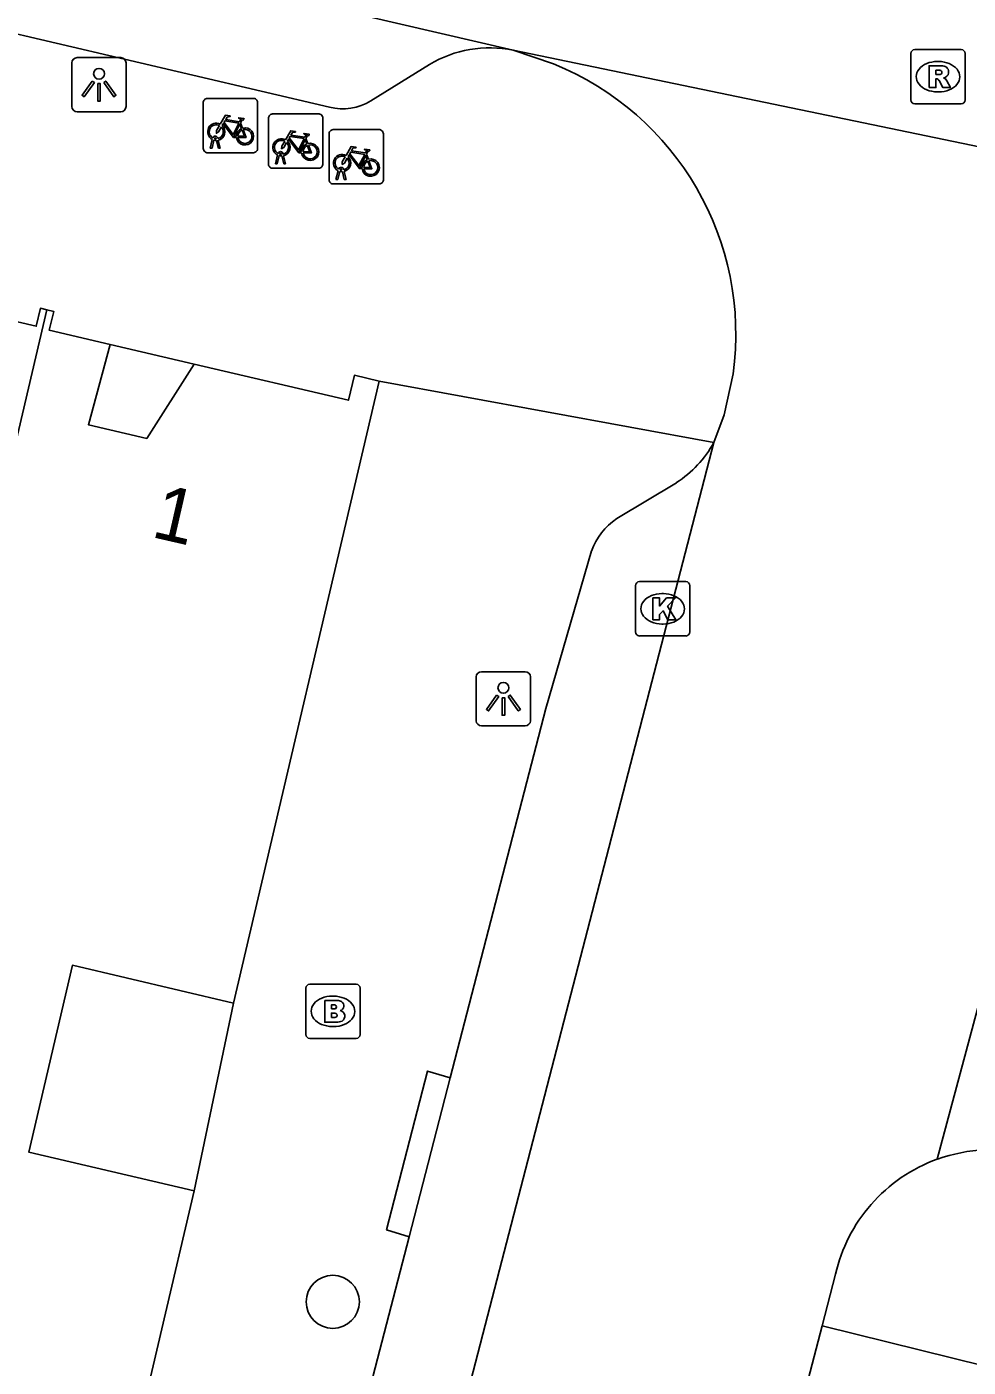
# Model space of a CAD drawing. Extents: x 163686 to 164493, y 382719 to 383870.
# Drawn here: x 163954.4 to 163971.73, y 383281.87 to 383306.54 of the extents above; entities that cross this region are included whole.
import ezdxf

# ---------------------------------------------------------------- set-up
doc = ezdxf.new("R2010")
doc.units = 0
for name, color, linetype in [('IMGEO_Boom', 7, 'Continuous'), ('IMGEO_Brandkraan', 7, 'Continuous'), ('IMGEO_Fietsenrek', 7, 'Continuous'), ('IMGEO_Groenvoorziening', 7, 'Continuous'), ('IMGEO_Kolk', 7, 'Continuous'), ('IMGEO_Lichtpunt', 7, 'Continuous'), ('IMGEO_Pand', 7, 'Continuous'), ('IMGEO_Pand_nummerreeks', 7, 'Continuous'), ('IMGEO_Pand_overbouw', 7, 'Continuous'), ('IMGEO_Rijbaan_lokaal_open', 7, 'Continuous'), ('IMGEO_Rioolput', 7, 'Continuous'), ('IMGEO_Voetpad_open', 7, 'Continuous')]:
    doc.layers.add(name, color=color, linetype=linetype)

msp = doc.modelspace()

# ---------------------------------------------------------------- linework, layer by layer
at = {"layer": 'IMGEO_Boom'}
msp.add_circle((163960.029, 383283.075), 0.489, dxfattribs=at)
at = {"layer": 'IMGEO_Brandkraan'}
for p, q in [((163959.532, 383287.995), (163959.532, 383288.847)), ((163959.607, 383288.921), (163960.459, 383288.921)), ((163960.533, 383288.847), (163960.533, 383287.995)), ((163960.02, 383288.701), (163960.045, 383288.701)), ((163960.043, 383288.141), (163960.018, 383288.141)), ((163960.459, 383287.921), (163959.607, 383287.921))]:
    msp.add_line(p, q, dxfattribs=at)
for points in [[(163959.532, 383287.995), (163959.532, 383288.847)], [(163959.607, 383288.921), (163960.459, 383288.921)], [(163960.533, 383288.847), (163960.533, 383287.995)], [(163959.88, 383288.621), (163959.88, 383288.221), (163960.093, 383288.221)], [(163960.111, 383288.621), (163959.88, 383288.621)], [(163960.059, 383288.54), (163960.005, 383288.54), (163960.005, 383288.464)], [(163960.005, 383288.464), (163960.058, 383288.464)], [(163960.067, 383288.388), (163960.005, 383288.388), (163960.005, 383288.307)], [(163960.005, 383288.307), (163960.067, 383288.307)], [(163960.459, 383287.921), (163959.607, 383287.921)]]:
    msp.add_lwpolyline(points, dxfattribs=at)
for centre, radius, start, end in [((163959.609, 383288.845), 0.0765, 91.552, 178.448), ((163959.609, 383288.845), 0.0765, 91.552, 178.448), ((163960.457, 383288.845), 0.0765, 1.552, 88.448), ((163960.457, 383288.845), 0.0765, 1.552, 88.448), ((163960.115, 383288.476), 0.145, 59.4692, 91.5367), ((163960.14, 383288.523), 0.0922, 285.5137, 58.1501), ((163960.06, 383288.502), 0.0379, 267.8285, 90.9355), ((163960.068, 383288.347), 0.0404, 269.8759, 90.5077), ((163960.145, 383288.331), 0.105, 301.3115, 78.989), ((163960.099, 383288.472), 0.251, 268.6676, 293.5347), ((163959.609, 383287.997), 0.0765, 181.552, 268.448), ((163959.609, 383287.997), 0.0765, 181.552, 268.448), ((163960.457, 383287.997), 0.0765, 271.552, 358.448), ((163960.457, 383287.997), 0.0765, 271.552, 358.448)]:
    msp.add_arc(centre, radius, start, end, dxfattribs=at)
for centre, major_axis, ratio, start_param, end_param in [((163960.019, 383288.421), (-0.387, 0.002), 0.722429, 4.712389, 7.853982), ((163960.044, 383288.421), (-0.39, 0.002), 0.717154, 1.570796, 4.712389)]:
    msp.add_ellipse(centre, major_axis=major_axis, ratio=ratio, start_param=start_param, end_param=end_param, dxfattribs=at)
at = {"layer": 'IMGEO_Fietsenrek'}
for p, q in [((163957.645, 383304.298), (163957.645, 383305.139)), ((163957.645, 383305.139), (163957.645, 383304.298)), ((163957.72, 383305.223), (163958.561, 383305.223)), ((163958.561, 383305.223), (163957.72, 383305.223)), ((163958.645, 383305.148), (163958.645, 383304.307)), ((163958.645, 383304.307), (163958.645, 383305.148)), ((163958.921, 383304.937), (163959.762, 383304.937)), ((163959.762, 383304.937), (163958.921, 383304.937)), ((163958.332, 383304.772), (163958.368, 383304.677)), ((163958.846, 383304.012), (163958.846, 383304.853)), ((163958.846, 383304.853), (163958.846, 383304.012)), ((163959.846, 383304.862), (163959.846, 383304.021)), ((163959.846, 383304.021), (163959.846, 383304.862)), ((163960.036, 383304.648), (163960.877, 383304.648)), ((163960.877, 383304.648), (163960.036, 383304.648)), ((163957.772, 383304.307), (163957.811, 383304.467)), ((163957.841, 383304.455), (163957.806, 383304.307)), ((163957.883, 383304.479), (163957.882, 383304.483)), ((163957.924, 383304.307), (163957.89, 383304.449)), ((163957.914, 383304.49), (163957.915, 383304.483)), ((163957.922, 383304.453), (163957.957, 383304.307)), ((163959.533, 383304.486), (163959.569, 383304.391)), ((163959.961, 383303.723), (163959.961, 383304.564)), ((163959.961, 383304.564), (163959.961, 383303.723)), ((163960.961, 383304.573), (163960.961, 383303.732)), ((163960.961, 383303.732), (163960.961, 383304.573)), ((163958.57, 383304.223), (163957.729, 383304.223)), ((163957.729, 383304.223), (163958.57, 383304.223)), ((163957.806, 383304.307), (163957.772, 383304.307)), ((163957.957, 383304.307), (163957.924, 383304.307)), ((163958.973, 383304.021), (163959.012, 383304.181)), ((163959.042, 383304.169), (163959.007, 383304.021)), ((163959.084, 383304.193), (163959.083, 383304.197)), ((163959.125, 383304.021), (163959.091, 383304.163)), ((163959.115, 383304.204), (163959.116, 383304.197)), ((163959.123, 383304.167), (163959.158, 383304.021)), ((163960.648, 383304.197), (163960.684, 383304.102)), ((163959.771, 383303.937), (163958.93, 383303.937)), ((163958.93, 383303.937), (163959.771, 383303.937)), ((163959.007, 383304.021), (163958.973, 383304.021)), ((163959.158, 383304.021), (163959.125, 383304.021)), ((163960.088, 383303.732), (163960.127, 383303.892)), ((163960.157, 383303.88), (163960.122, 383303.732)), ((163960.199, 383303.904), (163960.198, 383303.908)), ((163960.23, 383303.915), (163960.231, 383303.908)), ((163960.238, 383303.878), (163960.273, 383303.732)), ((163960.886, 383303.648), (163960.045, 383303.648)), ((163960.045, 383303.648), (163960.886, 383303.648)), ((163960.122, 383303.732), (163960.088, 383303.732)), ((163960.24, 383303.732), (163960.206, 383303.874)), ((163960.273, 383303.732), (163960.24, 383303.732))]:
    msp.add_line(p, q, dxfattribs=at)
for points in [[(163957.958, 383304.749), (163958.053, 383304.913), (163958.139, 383304.899), (163958.141, 383304.89), (163958.085, 383304.879), (163958.058, 383304.834), (163958.314, 383304.793)], [(163958.314, 383304.793), (163958.339, 383304.842), (163958.333, 383304.846), (163958.31, 383304.85), (163958.298, 383304.857), (163958.297, 383304.86), (163958.299, 383304.865), (163958.394, 383304.85), (163958.396, 383304.84), (163958.386, 383304.827), (163958.374, 383304.821), (163958.36, 383304.827), (163958.332, 383304.772)], [(163957.979, 383304.697), (163957.927, 383304.607), (163957.887, 383304.582), (163957.888, 383304.629), (163957.943, 383304.723)], [(163958.254, 383304.505), (163958.204, 383304.505), (163958.013, 383304.756), (163957.994, 383304.724)], [(163958.301, 383304.768), (163958.044, 383304.809), (163958.027, 383304.78), (163958.194, 383304.56), (163958.301, 383304.768)], [(163958.349, 383304.67), (163958.319, 383304.747), (163958.21, 383304.529), (163958.253, 383304.529)], [(163958.283, 383304.529), (163958.403, 383304.528), (163958.359, 383304.642)], [(163958.379, 383304.649), (163958.434, 383304.504), (163958.284, 383304.504)], [(163959.159, 383304.463), (163959.254, 383304.627), (163959.34, 383304.613), (163959.342, 383304.604), (163959.286, 383304.593), (163959.259, 383304.548), (163959.515, 383304.507)], [(163959.18, 383304.411), (163959.128, 383304.321), (163959.088, 383304.296), (163959.089, 383304.343), (163959.144, 383304.437)], [(163959.455, 383304.219), (163959.405, 383304.219), (163959.214, 383304.47), (163959.195, 383304.438)], [(163959.502, 383304.482), (163959.245, 383304.523), (163959.228, 383304.494), (163959.395, 383304.274), (163959.502, 383304.482)], [(163959.55, 383304.384), (163959.52, 383304.461), (163959.411, 383304.243), (163959.454, 383304.243)], [(163959.515, 383304.507), (163959.54, 383304.556), (163959.534, 383304.56), (163959.511, 383304.564), (163959.499, 383304.571), (163959.498, 383304.574), (163959.5, 383304.579), (163959.595, 383304.564), (163959.597, 383304.554), (163959.587, 383304.541), (163959.575, 383304.535), (163959.561, 383304.541), (163959.533, 383304.486)], [(163959.484, 383304.243), (163959.604, 383304.242), (163959.56, 383304.356)], [(163959.58, 383304.363), (163959.635, 383304.218), (163959.485, 383304.218)], [(163960.295, 383304.122), (163960.243, 383304.032), (163960.203, 383304.007), (163960.204, 383304.054), (163960.259, 383304.148)], [(163960.274, 383304.174), (163960.369, 383304.338), (163960.455, 383304.324), (163960.457, 383304.315), (163960.401, 383304.304), (163960.374, 383304.259), (163960.63, 383304.218)], [(163960.57, 383303.93), (163960.52, 383303.93), (163960.329, 383304.181), (163960.31, 383304.149)], [(163960.617, 383304.193), (163960.36, 383304.234), (163960.343, 383304.205), (163960.51, 383303.985), (163960.617, 383304.193)], [(163960.665, 383304.095), (163960.635, 383304.172), (163960.526, 383303.954), (163960.569, 383303.954)], [(163960.63, 383304.218), (163960.655, 383304.267), (163960.649, 383304.271), (163960.626, 383304.275), (163960.614, 383304.282), (163960.613, 383304.285), (163960.615, 383304.29), (163960.71, 383304.275), (163960.712, 383304.265), (163960.702, 383304.252), (163960.69, 383304.246), (163960.676, 383304.252), (163960.648, 383304.197)], [(163960.599, 383303.954), (163960.719, 383303.953), (163960.675, 383304.067)], [(163960.695, 383304.074), (163960.75, 383303.929), (163960.6, 383303.929)]]:
    msp.add_lwpolyline(points, dxfattribs=at)
for centre, radius, start, end in [((163957.723, 383305.145), 0.0779, 92.4484, 184.2845), ((163957.723, 383305.145), 0.0779, 92.4484, 184.2845), ((163958.567, 383305.145), 0.0779, 2.4484, 94.2845), ((163958.567, 383305.145), 0.0779, 2.4484, 94.2845), ((163958.924, 383304.859), 0.0779, 92.4484, 184.2845), ((163958.924, 383304.859), 0.0779, 92.4484, 184.2845), ((163959.768, 383304.859), 0.0779, 2.4484, 94.2845), ((163959.768, 383304.859), 0.0779, 2.4484, 94.2845), ((163957.885, 383304.608), 0.159, 62.6766, 242.1369), ((163957.885, 383304.608), 0.129, 63.3192, 238.903), ((163957.885, 383304.608), 0.129, 283.6043, 43.4302), ((163957.885, 383304.608), 0.159, 283.5766, 46.6042), ((163958.412, 383304.524), 0.159, 113.3408, 178.3217), ((163958.412, 383304.524), 0.159, 187.0065, 105.7708), ((163958.412, 383304.524), 0.129, 113.923, 177.9556), ((163958.412, 383304.524), 0.129, 188.6715, 104.5883), ((163960.039, 383304.57), 0.0779, 92.4484, 184.2845), ((163960.039, 383304.57), 0.0779, 92.4484, 184.2845), ((163960.883, 383304.57), 0.0779, 2.4484, 94.2845), ((163960.883, 383304.57), 0.0779, 2.4484, 94.2845), ((163957.865, 383304.479), 0.0499, 12.8025, 158.6934), ((163957.885, 383304.608), 0.159, 253.9967, 271.7867), ((163957.865, 383304.479), 0.0174, 12.8025, 163.4502), ((163957.885, 383304.608), 0.129, 253.415, 269.0204), ((163959.086, 383304.322), 0.159, 62.6766, 242.1369), ((163959.086, 383304.322), 0.129, 63.3192, 238.903), ((163959.086, 383304.322), 0.129, 283.6043, 43.4302), ((163959.086, 383304.322), 0.159, 283.5766, 46.6042), ((163959.613, 383304.238), 0.159, 113.3408, 178.3217), ((163959.613, 383304.238), 0.159, 187.0065, 105.7708), ((163957.723, 383304.301), 0.0779, 182.4484, 274.2845), ((163957.723, 383304.301), 0.0779, 182.4484, 274.2845), ((163958.567, 383304.301), 0.0779, 272.4484, 4.2845), ((163958.567, 383304.301), 0.0779, 272.4484, 4.2845), ((163959.066, 383304.193), 0.0499, 12.8025, 158.6934), ((163959.086, 383304.322), 0.159, 253.9967, 271.7867), ((163959.066, 383304.193), 0.0174, 12.8025, 163.4502), ((163959.086, 383304.322), 0.129, 253.415, 269.0204), ((163959.613, 383304.238), 0.129, 113.923, 177.9556), ((163959.613, 383304.238), 0.129, 188.6715, 104.5883), ((163960.201, 383304.033), 0.159, 62.6766, 242.1369), ((163960.201, 383304.033), 0.129, 63.3192, 238.903), ((163960.201, 383304.033), 0.159, 283.5766, 46.6042), ((163958.924, 383304.015), 0.0779, 182.4484, 274.2845), ((163958.924, 383304.015), 0.0779, 182.4484, 274.2845), ((163959.768, 383304.015), 0.0779, 272.4484, 4.2845), ((163959.768, 383304.015), 0.0779, 272.4484, 4.2845), ((163960.181, 383303.904), 0.0499, 12.8025, 158.6934), ((163960.201, 383304.033), 0.159, 253.9967, 271.7867), ((163960.181, 383303.904), 0.0174, 12.8025, 163.4502), ((163960.201, 383304.033), 0.129, 253.415, 269.0204), ((163960.201, 383304.033), 0.129, 283.6043, 43.4302), ((163960.728, 383303.949), 0.159, 113.3408, 178.3217), ((163960.728, 383303.949), 0.159, 187.0065, 105.7708), ((163960.728, 383303.949), 0.129, 113.923, 177.9556), ((163960.728, 383303.949), 0.129, 188.6715, 104.5883), ((163960.039, 383303.726), 0.0779, 182.4484, 274.2845), ((163960.039, 383303.726), 0.0779, 182.4484, 274.2845), ((163960.883, 383303.726), 0.0779, 272.4484, 4.2845), ((163960.883, 383303.726), 0.0779, 272.4484, 4.2845)]:
    msp.add_arc(centre, radius, start, end, dxfattribs=at)
at = {"layer": 'IMGEO_Groenvoorziening'}
msp.add_lwpolyline([(163969.037, 383282.636), (163976.803, 383280.714)], dxfattribs=at)
at = {"layer": 'IMGEO_Kolk'}
for p, q in [((163965.601, 383295.403), (163965.601, 383296.255)), ((163965.676, 383296.329), (163966.528, 383296.329)), ((163966.602, 383296.255), (163966.602, 383295.403)), ((163966.089, 383296.109), (163966.114, 383296.109)), ((163966.112, 383295.549), (163966.087, 383295.549)), ((163966.528, 383295.329), (163965.676, 383295.329))]:
    msp.add_line(p, q, dxfattribs=at)
for points in [[(163965.601, 383295.403), (163965.601, 383296.255)], [(163965.676, 383296.329), (163966.528, 383296.329)], [(163966.602, 383296.255), (163966.602, 383295.403)], [(163965.922, 383296.029), (163966.045, 383296.029), (163966.045, 383295.878), (163966.175, 383296.029), (163966.339, 383296.029), (163966.193, 383295.878), (163966.346, 383295.629), (163966.194, 383295.629), (163966.109, 383295.793), (163966.045, 383295.726), (163966.045, 383295.629), (163965.922, 383295.629), (163965.922, 383296.029)], [(163966.528, 383295.329), (163965.676, 383295.329)]]:
    msp.add_lwpolyline(points, dxfattribs=at)
for centre, start, end in [((163965.678, 383296.253), 91.552, 178.448), ((163965.678, 383296.253), 91.552, 178.448), ((163966.526, 383296.253), 1.552, 88.448), ((163966.526, 383296.253), 1.552, 88.448), ((163965.678, 383295.405), 181.552, 268.448), ((163965.678, 383295.405), 181.552, 268.448), ((163966.526, 383295.405), 271.552, 358.448), ((163966.526, 383295.405), 271.552, 358.448)]:
    msp.add_arc(centre, 0.0765, start, end, dxfattribs=at)
for centre, major_axis, ratio, start_param, end_param in [((163966.088, 383295.829), (-0.387, 0.002), 0.722429, 4.712389, 7.853982), ((163966.113, 383295.829), (-0.39, 0.002), 0.717154, 1.570796, 4.712389)]:
    msp.add_ellipse(centre, major_axis=major_axis, ratio=ratio, start_param=start_param, end_param=end_param, dxfattribs=at)
at = {"layer": 'IMGEO_Lichtpunt'}
for p, q in [((163955.227, 383305.878), (163955.227, 383305.071)), ((163955.227, 383305.878), (163955.227, 383305.071)), ((163956.129, 383305.973), (163955.321, 383305.973)), ((163956.129, 383305.973), (163955.321, 383305.973)), ((163956.223, 383305.071), (163956.223, 383305.878)), ((163956.223, 383305.071), (163956.223, 383305.878)), ((163955.321, 383304.977), (163956.129, 383304.977)), ((163955.321, 383304.977), (163956.129, 383304.977)), ((163962.671, 383294.577), (163962.671, 383293.77)), ((163962.671, 383294.577), (163962.671, 383293.77)), ((163963.573, 383294.672), (163962.765, 383294.672)), ((163963.573, 383294.672), (163962.765, 383294.672)), ((163963.667, 383293.77), (163963.667, 383294.577)), ((163963.667, 383293.77), (163963.667, 383294.577)), ((163962.765, 383293.676), (163963.573, 383293.676)), ((163962.765, 383293.676), (163963.573, 383293.676))]:
    msp.add_line(p, q, dxfattribs=at)
for points in [[(163955.601, 383305.542), (163955.64, 383305.514), (163955.452, 383305.252), (163955.414, 383305.279), (163955.601, 383305.542)], [(163955.703, 383305.494), (163955.75, 383305.494), (163955.75, 383305.172), (163955.703, 383305.172), (163955.703, 383305.494)], [(163955.813, 383305.514), (163955.851, 383305.541), (163956.038, 383305.279), (163955.999, 383305.251), (163955.813, 383305.514)], [(163963.045, 383294.241), (163963.084, 383294.213), (163962.896, 383293.951), (163962.858, 383293.978), (163963.045, 383294.241)], [(163963.147, 383294.193), (163963.194, 383294.193), (163963.194, 383293.871), (163963.147, 383293.871), (163963.147, 383294.193)], [(163963.257, 383294.213), (163963.295, 383294.24), (163963.482, 383293.978), (163963.443, 383293.95), (163963.257, 383294.213)]]:
    msp.add_lwpolyline(points, dxfattribs=at)
for centre in [(163955.726, 383305.676), (163963.17, 383294.375)]:
    msp.add_circle(centre, 0.0994, dxfattribs=at)
for centre, start, end in [((163955.321, 383305.878), 90, 180), ((163955.321, 383305.878), 90, 180), ((163956.129, 383305.878), 0, 90), ((163956.129, 383305.878), 0, 90), ((163955.321, 383305.071), 180, 270), ((163955.321, 383305.071), 180, 270), ((163956.129, 383305.071), 270, 0), ((163956.129, 383305.071), 270, 360), ((163962.765, 383294.577), 90, 180), ((163962.765, 383294.577), 90, 180), ((163963.573, 383294.577), 0, 90), ((163963.573, 383294.577), 0, 90), ((163962.765, 383293.77), 180, 270), ((163962.765, 383293.77), 180, 270), ((163963.573, 383293.77), 270, 0), ((163963.573, 383293.77), 270, 360)]:
    msp.add_arc(centre, 0.0946, start, end, dxfattribs=at)
at = {"layer": 'IMGEO_Pand'}
for points in [[(163950.115, 383281.484), (163954.768, 383301.331)], [(163953.45, 383301.291), (163954.57, 383301.029), (163954.647, 383301.36), (163954.768, 383301.331)], [(163954.768, 383301.331), (163954.892, 383301.302), (163954.811, 383300.957), (163955.931, 383300.695)], [(163957.48, 383300.332), (163956.604, 383298.966), (163955.532, 383299.217), (163955.931, 383300.695)], [(163957.48, 383300.332), (163960.318, 383299.668), (163960.426, 383300.126), (163960.883, 383300.019)], [(163960.883, 383300.019), (163958.202, 383288.573)], [(163957.478, 383285.118), (163954.432, 383285.831), (163955.237, 383289.268), (163958.202, 383288.573)], [(163957.478, 383285.118), (163956.288, 383280.038)]]:
    msp.add_lwpolyline(points, dxfattribs=at)
at = {"layer": 'IMGEO_Pand_overbouw'}
msp.add_lwpolyline([(163957.48, 383300.332), (163955.931, 383300.695), (163955.532, 383299.217), (163956.604, 383298.966)], close=True, dxfattribs=at)
at = {"layer": 'IMGEO_Rijbaan_lokaal_open'}
for points in [[(163918.723, 383316.558), (163938.848, 383311.785), (163963.348, 383306.111)], [(163963.348, 383306.111), (163974.919, 383303.713)], [(163963.348, 383306.111), (163964.093, 383305.857)], [(163967.398, 383300.156), (163967.235, 383299.396), (163967.043, 383298.891)], [(163967.043, 383298.891), (163932.475, 383165.499)], [(163972.961, 383292.415), (163971.158, 383285.7)], [(163969.037, 383282.636), (163969.285, 383283.585)], [(163966.882, 383274.38), (163969.037, 383282.636)]]:
    msp.add_lwpolyline(points, dxfattribs=at)
for centre, radius, start, end in [((163962.087, 383300.885), 5.361, 352.1792, 68.0245), ((163972.16, 383282.913), 2.961, 75.0235, 109.7726), ((163972.165, 383282.92), 2.957, 109.9113, 138.8662), ((163972.142, 383282.934), 2.93, 138.7778, 167.1648)]:
    msp.add_arc(centre, radius, start, end, dxfattribs=at)
at = {"layer": 'IMGEO_Rioolput'}
for p, q in [((163970.745, 383306.122), (163971.597, 383306.122)), ((163970.67, 383305.196), (163970.67, 383306.048)), ((163971.158, 383305.902), (163971.183, 383305.902)), ((163971.671, 383306.048), (163971.671, 383305.196)), ((163971.597, 383305.122), (163970.745, 383305.122)), ((163971.181, 383305.342), (163971.156, 383305.342))]:
    msp.add_line(p, q, dxfattribs=at)
for points in [[(163970.745, 383306.122), (163971.597, 383306.122)], [(163970.67, 383305.196), (163970.67, 383306.048)], [(163971.671, 383306.048), (163971.671, 383305.196)], [(163971.259, 383305.82), (163971.007, 383305.822), (163971.007, 383305.422)], [(163971.185, 383305.741), (163971.131, 383305.741), (163971.131, 383305.66)], [(163971.131, 383305.66), (163971.183, 383305.66)], [(163971.007, 383305.422), (163971.131, 383305.422), (163971.131, 383305.584), (163971.142, 383305.584)], [(163971.189, 383305.555), (163971.26, 383305.422), (163971.4, 383305.422), (163971.335, 383305.548)], [(163971.597, 383305.122), (163970.745, 383305.122)]]:
    msp.add_lwpolyline(points, dxfattribs=at)
for centre, radius, start, end in [((163970.747, 383306.046), 0.0765, 91.552, 178.448), ((163970.747, 383306.046), 0.0765, 91.552, 178.448), ((163971.595, 383306.046), 0.0765, 1.552, 88.448), ((163971.595, 383306.046), 0.0765, 1.552, 88.448), ((163971.167, 383305.849), 0.19, 274.7715, 282.9687), ((163971.191, 383305.645), 0.0964, 77.0061, 93.1865), ((163971.205, 383305.702), 0.0378, 276.6634, 79.6772), ((163971.258, 383305.71), 0.109, 350.3612, 89.416), ((163971.256, 383305.71), 0.112, 277.5842, 350.9817), ((163971.141, 383305.531), 0.0533, 26.0293, 88.6989), ((163971.24, 383305.495), 0.108, 29.5134, 73.7905), ((163970.747, 383305.198), 0.0765, 181.552, 268.448), ((163970.747, 383305.198), 0.0765, 181.552, 268.448), ((163971.595, 383305.198), 0.0765, 271.552, 358.448), ((163971.595, 383305.198), 0.0765, 271.552, 358.448)]:
    msp.add_arc(centre, radius, start, end, dxfattribs=at)
for centre, major_axis, ratio, start_param, end_param in [((163971.157, 383305.622), (-0.387, 0.002), 0.722429, 4.712389, 7.853982), ((163971.182, 383305.622), (-0.39, 0.002), 0.717154, 1.570796, 4.712389)]:
    msp.add_ellipse(centre, major_axis=major_axis, ratio=ratio, start_param=start_param, end_param=end_param, dxfattribs=at)
at = {"layer": 'IMGEO_Voetpad_open'}
for points in [[(163959.97, 383305.061), (163920.968, 383314.195)], [(163961.809, 383305.848), (163960.729, 383305.176)], [(163955.931, 383300.695), (163957.48, 383300.332)], [(163967.043, 383298.891), (163960.883, 383300.019)], [(163965.257, 383297.49), (163966.354, 383298.15)], [(163962.191, 383287.199), (163963.949, 383293.994), (163964.791, 383296.893)], [(163958.202, 383288.573), (163957.478, 383285.118)], [(163961.434, 383284.273), (163961.021, 383284.398), (163961.773, 383287.32), (163962.191, 383287.199)], [(163962.191, 383287.199), (163961.434, 383284.273)], [(163960.14, 383279.284), (163961.434, 383284.273)]]:
    msp.add_lwpolyline(points, dxfattribs=at)
for centre, radius, start, end in [((163962.919, 383303.988), 2.166, 78.5713, 120.824), ((163960.211, 383306.034), 1.003, 256.1093, 301.122), ((163965.267, 383299.852), 2.019, 302.5722, 331.5929), ((163965.95, 383296.468), 1.235, 124.1635, 159.8875)]:
    msp.add_arc(centre, radius, start, end, dxfattribs=at)

# ---------------------------------------------------------------- texts
at = {"layer": 'IMGEO_Pand_nummerreeks'}
msp.add_text('1', height=1, rotation=347.074, dxfattribs=at).set_placement((163956.663, 383297.157))

doc.saveas('drawing.dxf')
